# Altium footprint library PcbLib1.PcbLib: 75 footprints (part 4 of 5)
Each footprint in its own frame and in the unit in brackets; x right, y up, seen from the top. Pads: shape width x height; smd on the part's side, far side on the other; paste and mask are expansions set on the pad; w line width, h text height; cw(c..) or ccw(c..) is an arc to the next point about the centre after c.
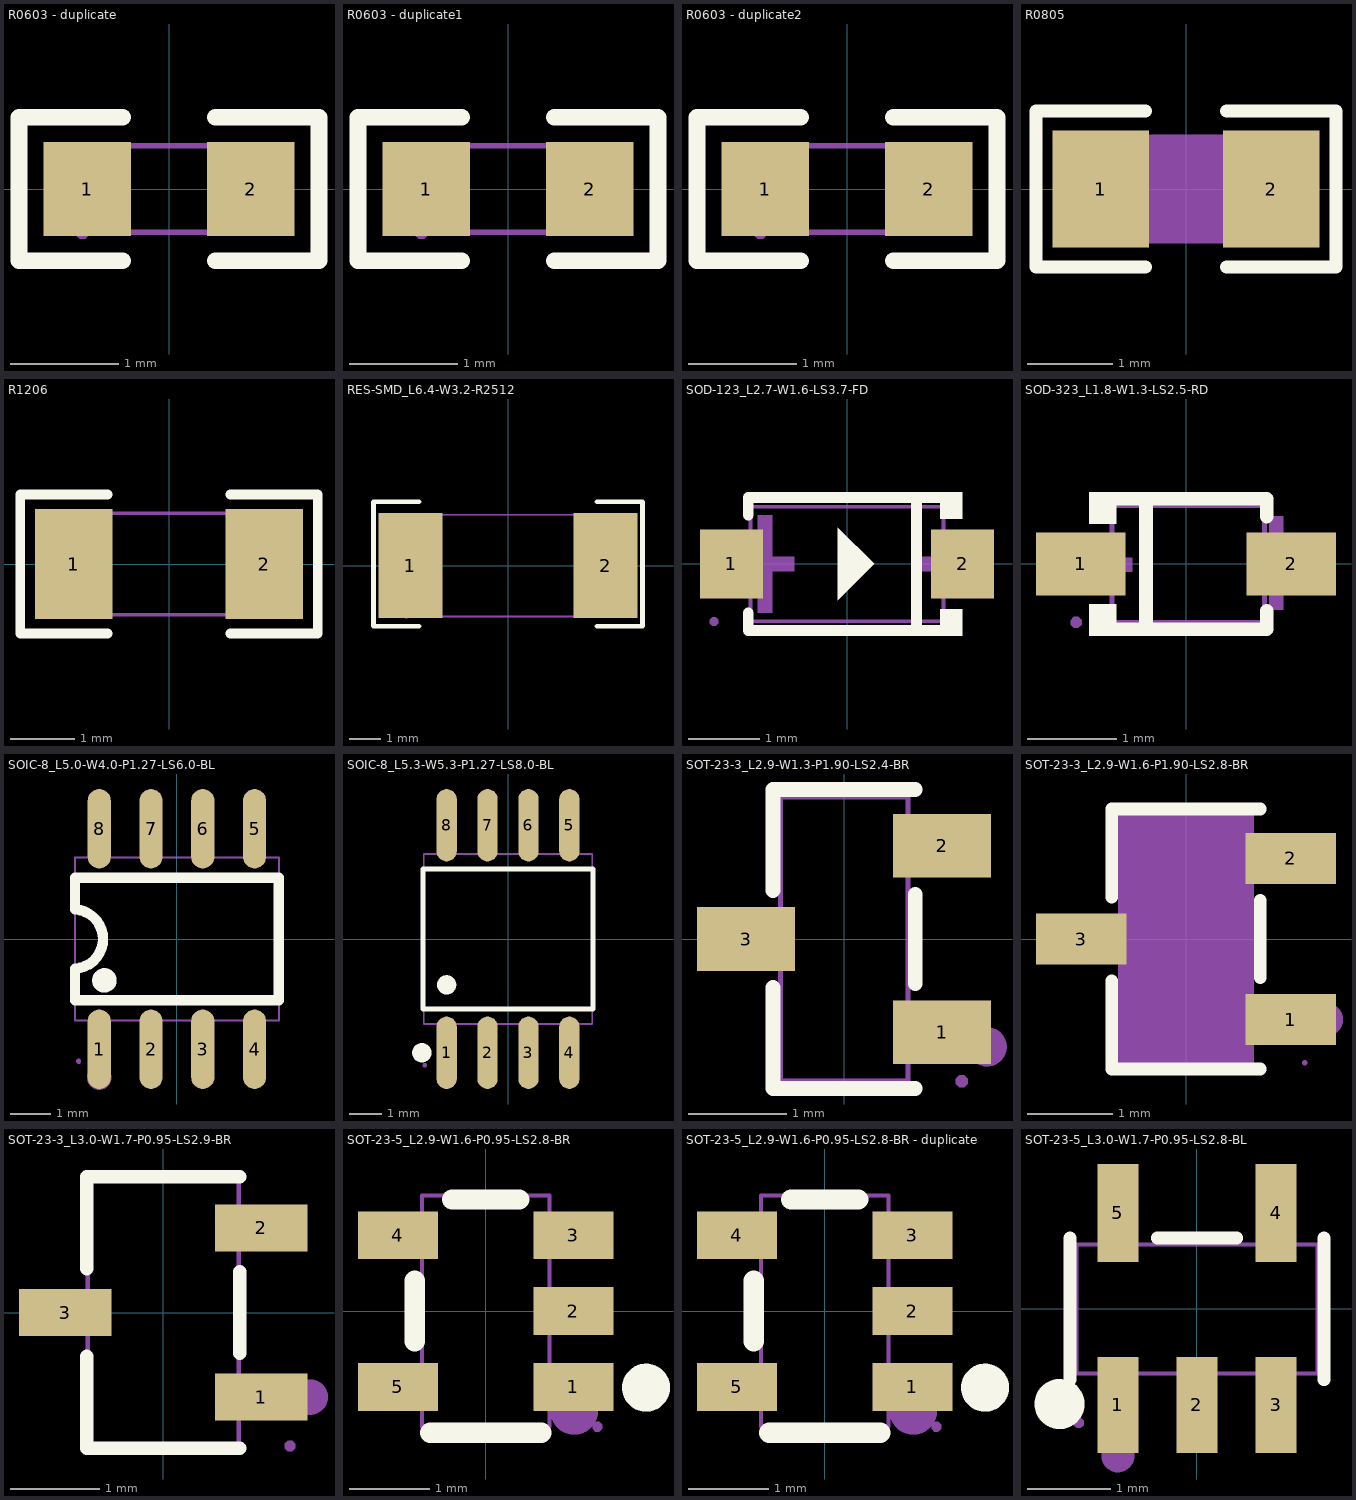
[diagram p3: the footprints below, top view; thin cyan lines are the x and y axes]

## R0603 - duplicate [mm]
pads (2):
  rect 0.806x0.864 smd paste-100 mask+0.051: 1(-0.753,0) 2(0.753,0)
Top Overlay:
  lines w0.152: -0.426,-0.661 -1.385,-0.661 -1.385,0.661 -0.426,0.661 ; 0.426,-0.661 1.385,-0.661 1.385,0.661 0.426,0.661
Top Paste:
  region: 1.195,0.45 0.395,0.45 0.345,0.4 0.345,0.172 0.715,0.172 0.715,-0.158 0.345,-0.158 0.345,-0.4 0.395,-0.45 1.195,-0.45 1.245,-0.4 1.245,0.4
  region: -1.195,-0.45 -0.395,-0.45 -0.345,-0.4 -0.345,-0.172 -0.715,-0.172 -0.715,0.158 -0.345,0.158 -0.345,0.4 -0.395,0.45 -1.195,0.45 -1.245,0.4 -1.245,-0.4
Mechanical 6:
  lines w0.051: -0.8,-0.4 -0.8,0.4 0.8,0.4 0.8,-0.4 -0.8,-0.4
Mechanical 8:
  region: -0.74,-0.4 -0.74,-0.425 -0.775,-0.46 -0.825,-0.46 -0.86,-0.425 -0.86,-0.4 -0.86,-0.375 -0.825,-0.34 -0.775,-0.34 -0.74,-0.375 -0.74,-0.4
Mechanical 9:
  region: -0.8,-0.4 -0.8,0.4 -0.5,0.4 -0.5,-0.4
  region: 0.8,-0.4 0.8,0.4 0.5,0.4 0.5,-0.4

## R0603 - duplicate1 [mm]
pads (2):
  rect 0.806x0.864 smd paste-100 mask+0.051: 1(-0.753,0) 2(0.753,0)
Top Overlay:
  lines w0.152: -0.426,-0.661 -1.385,-0.661 -1.385,0.661 -0.426,0.661 ; 0.426,-0.661 1.385,-0.661 1.385,0.661 0.426,0.661
Top Paste:
  region: -1.195,-0.45 -0.395,-0.45 -0.345,-0.4 -0.345,-0.172 -0.715,-0.172 -0.715,0.158 -0.345,0.158 -0.345,0.4 -0.395,0.45 -1.195,0.45 -1.245,0.4 -1.245,-0.4
  region: 1.195,0.45 0.395,0.45 0.345,0.4 0.345,0.172 0.715,0.172 0.715,-0.158 0.345,-0.158 0.345,-0.4 0.395,-0.45 1.195,-0.45 1.245,-0.4 1.245,0.4
Mechanical 6:
  lines w0.051: -0.8,-0.4 0.8,-0.4 0.8,0.4 -0.8,0.4 -0.8,-0.4
Mechanical 8:
  region: -0.74,-0.4 -0.74,-0.425 -0.775,-0.46 -0.825,-0.46 -0.86,-0.425 -0.86,-0.4 -0.86,-0.375 -0.825,-0.34 -0.775,-0.34 -0.74,-0.375 -0.74,-0.4
Mechanical 9:
  region: 0.8,-0.4 0.8,0.4 0.5,0.4 0.5,-0.4
  region: -0.8,-0.4 -0.8,0.4 -0.5,0.4 -0.5,-0.4

## R0603 - duplicate2 [mm]
pads (2):
  rect 0.806x0.864 smd paste-100 mask+0.051: 1(-0.753,0) 2(0.753,0)
Top Overlay:
  lines w0.152: -0.426,-0.661 -1.385,-0.661 -1.385,0.661 -0.426,0.661 ; 0.426,-0.661 1.385,-0.661 1.385,0.661 0.426,0.661
Top Paste:
  region: 1.195,0.45 0.395,0.45 0.345,0.4 0.345,0.172 0.715,0.172 0.715,-0.158 0.345,-0.158 0.345,-0.4 0.395,-0.45 1.195,-0.45 1.245,-0.4 1.245,0.4
  region: -1.195,-0.45 -0.395,-0.45 -0.345,-0.4 -0.345,-0.172 -0.715,-0.172 -0.715,0.158 -0.345,0.158 -0.345,0.4 -0.395,0.45 -1.195,0.45 -1.245,0.4 -1.245,-0.4
Mechanical 6:
  lines w0.051: -0.8,-0.4 -0.8,0.4 0.8,0.4 0.8,-0.4 -0.8,-0.4
Mechanical 8:
  region: -0.74,-0.4 -0.74,-0.425 -0.775,-0.46 -0.825,-0.46 -0.86,-0.425 -0.86,-0.4 -0.86,-0.375 -0.825,-0.34 -0.775,-0.34 -0.74,-0.375 -0.74,-0.4
Mechanical 9:
  region: -0.8,-0.4 -0.8,0.4 -0.5,0.4 -0.5,-0.4
  region: 0.8,-0.4 0.8,0.4 0.5,0.4 0.5,-0.4

## R0805 [mm]
pads (2):
  rect 1.133x1.377 smd paste-100 mask+0.051: 1(-1,0) 2(1,0)
Top Overlay:
  lines w0.152: -0.476,-0.917 -1.761,-0.917 -1.761,0.917 -0.476,0.917 ; 0.476,-0.917 1.761,-0.917 1.761,0.917 0.476,0.917
Top Paste:
  region: 0.45,-0.64 0.45,-0.22 0.895,-0.22 0.895,0.23 0.455,0.23 0.45,0.64 0.5,0.69 1.65,0.69 1.7,0.64 1.7,-0.64 1.65,-0.69 0.5,-0.69
  region: -1.7,-0.64 -1.7,0.64 -1.65,0.69 -0.5,0.69 -0.45,0.64 -0.445,0.23 -0.895,0.23 -0.895,-0.22 -0.455,-0.22 -0.45,-0.64 -0.5,-0.69 -1.65,-0.69
Mechanical 9:
  region: -1,-0.637 -1,0.637 1,0.637 1,-0.637
Mechanical 11:
  region: -0.97,-0.638 -0.97,-0.65 -0.988,-0.668 -1.012,-0.668 -1.03,-0.65 -1.03,-0.638 -1.03,-0.625 -1.012,-0.608 -0.988,-0.608 -0.97,-0.625 -0.97,-0.638
Mechanical 12:
  region: 1,-0.637 1,0.637 0.6,0.637 0.6,-0.637
  region: -1,-0.637 -1,0.637 -0.6,0.637 -0.6,-0.637

## R1206 [mm]
pads (2):
  rect 1.208x1.701 smd paste-100 mask+0.051: 1(-1.479,0) 2(1.479,0)
Top Overlay:
  lines w0.152: -0.951,-1.079 -2.311,-1.079 -2.311,1.079 -0.951,1.079 ; 0.951,-1.079 2.311,-1.079 2.311,1.079 0.951,1.079
Top Paste:
  region: 0.875,-0.75 0.875,-0.389 0.975,-0.289 1.186,-0.289 1.286,-0.189 1.286,0.189 1.186,0.289 0.975,0.289 0.875,0.389 0.875,0.75 0.975,0.85 1.983,0.85 2.083,0.75 2.083,-0.75 1.983,-0.85 0.975,-0.85
  region: -0.875,-0.75 -0.875,-0.389 -0.975,-0.289 -1.186,-0.289 -1.286,-0.189 -1.286,0.189 -1.186,0.289 -0.975,0.289 -0.875,0.389 -0.875,0.75 -0.975,0.85 -1.983,0.85 -2.083,0.75 -2.083,-0.75 -1.983,-0.85 -0.975,-0.85
Mechanical 6:
  lines w0.051: -1.55,-0.788 -1.55,0.788 1.55,0.788 1.55,-0.788 -1.55,-0.788
Mechanical 8:
  region: -1.49,-0.787 -1.49,-0.812 -1.525,-0.847 -1.575,-0.847 -1.61,-0.812 -1.61,-0.787 -1.61,-0.763 -1.575,-0.727 -1.525,-0.727 -1.49,-0.763 -1.49,-0.787
Mechanical 9:
  region: -1.55,-0.788 -1.55,0.788 -1.1,0.788 -1.1,-0.788
  region: 1.55,-0.788 1.55,0.788 1.1,0.788 1.1,-0.788

## RES-SMD_L6.4-W3.2-R2512 [mm]
pads (2):
  rect 2x3.3 smd: 1(-3.066,0) 2(3.066,0)
Top Overlay:
  lines w0.152: -2.794,-1.905 -4.229,-1.905 -4.229,2.008 -2.794,2.008 ; 2.794,-1.905 4.229,-1.905 4.229,2.008 2.794,2.008
Mechanical 6:
  lines w0.051: -3.2,-1.6 -3.2,1.6 3.2,1.6 3.2,-1.6 -3.2,-1.6
Mechanical 8:
  region: -3.14,-1.6 -3.14,-1.625 -3.175,-1.66 -3.225,-1.66 -3.26,-1.625 -3.26,-1.6 -3.26,-1.575 -3.225,-1.54 -3.175,-1.54 -3.14,-1.575 -3.14,-1.6
Mechanical 9:
  region: -3.199,1.6 -2.299,1.6 -2.299,-1.6 -3.199,-1.6
  region: 2.299,1.6 3.199,1.6 3.199,-1.6 2.299,-1.6

## SOD-123_L2.7-W1.6-LS3.7-FD [mm]
pads (2):
  rect 0.88x0.96 smd: 1(-1.61,0) 2(1.61,0)
Top Overlay:
  region: 0.381,0 -0.127,0.508 -0.127,-0.508
  region: 1.3,1.002 1.3,0.632 1.605,0.632 1.605,1.002
  region: 1.3,-1.003 1.3,-0.632 1.605,-0.633 1.605,-1.003
  lines w0.152: -1.376,-0.683 -1.376,-0.926 1.376,-0.926 ; -1.376,0.683 -1.376,0.926 1.376,0.926 ; 0.967,-0.926 0.967,0.926
Mechanical 2:
  region: -1.245,-0.68 -1.245,0.68 -1.041,0.68 -1.041,-0.68
  region: -1.551,-0.102 -1.551,0.102 -0.735,0.102 -0.735,-0.102
  region: 1.805,-0.102 1.805,0.102 0.989,0.102 0.989,-0.102
Mechanical 6:
  lines w0.051: -1.345,-0.8 -1.345,0.8 1.345,0.8 1.345,-0.8 -1.345,-0.8
Mechanical 7:
  region: -1.511,0.3 -1.511,-0.3 -1.34,-0.3 -1.34,0.3
  region: 1.511,-0.3 1.511,0.3 1.34,0.3 1.34,-0.3
Mechanical 8:
  region: -1.791,-0.8 -1.791,-0.825 -1.826,-0.86 -1.876,-0.86 -1.911,-0.825 -1.911,-0.8 -1.911,-0.775 -1.876,-0.74 -1.826,-0.74 -1.791,-0.775 -1.791,-0.8
Mechanical 9:
  region: -1.851,0.3 -1.501,0.3 -1.501,-0.3 -1.851,-0.3
  region: 1.851,-0.3 1.501,-0.3 1.501,0.3 1.851,0.3

## SOD-323_L1.8-W1.3-LS2.5-RD [mm]
pads (2):
  rect 1x0.7 smd: 1(-1.172,0) 2(1.172,0)
Top Overlay:
  region: -0.775,0.802 -0.775,0.45 -1.08,0.45 -1.08,0.802
  region: -0.775,-0.803 -0.775,-0.45 -1.08,-0.45 -1.08,-0.803
  lines w0.152: -0.851,-0.726 0.901,-0.726 0.901,-0.52 ; -0.851,0.726 0.901,0.726 0.901,0.53 ; -0.447,-0.726 -0.447,0.726
Mechanical 2:
  region: -1.225,0.07 -1.225,-0.086 -0.601,-0.086 -0.601,0.07
  region: 1.315,0.09 1.315,-0.066 0.691,-0.066 0.691,0.09
  region: 1.083,0.53 1.083,-0.51 0.927,-0.51 0.927,0.53
Mechanical 6:
  lines w0.051: -0.825,-0.65 -0.825,0.65 0.875,0.65 0.875,-0.65 -0.825,-0.65
Mechanical 7:
  region: 0.985,0.16 0.985,-0.16 0.865,-0.16 0.865,0.16
  region: -0.815,0.16 -0.815,-0.16 -0.935,-0.16 -0.935,0.16
Mechanical 8:
  region: -1.165,-0.65 -1.165,-0.675 -1.2,-0.71 -1.25,-0.71 -1.285,-0.675 -1.285,-0.65 -1.285,-0.625 -1.25,-0.59 -1.2,-0.59 -1.165,-0.625 -1.165,-0.65
Mechanical 9:
  region: 1.275,0.16 1.275,-0.16 0.975,-0.16 0.975,0.16
  region: -0.925,0.16 -0.925,-0.16 -1.225,-0.16 -1.225,0.16

## SOIC-8_L5.0-W4.0-P1.27-LS6.0-BL [mil]
pads (8):
  oval 22.38x76.78 smd: 1(-75,-106.5) 2(-25,-106.5) 3(25,-106.5) 4(75,-106.5) 5(75,106.5) 6(25,106.5) 7(-25,106.5) 8(-75,106.5)
Top Overlay:
  circle w11.81: c-70,-40 r5.91
  lines w10: -98.43,-28.61 ccw(c-99.99,0) -98.23,28.59 ; -98.42,-28.61 -98.42,-59.05 98.42,-59.05 98.42,59.05 -98.42,59.05 -98.42,28.59
Mechanical 2:
  circle w11.81: c-75,-133.86 r5.91
Mechanical 6:
  lines w2: -98.42,-78.74 98.42,-78.74 98.42,78.74 -98.42,78.74 -98.42,-78.74
Mechanical 7:
  region: -83.07,-85.63 -83.07,-76.38 -66.93,-76.38 -66.93,-85.63
  region: -33.07,-85.63 -33.07,-76.38 -16.93,-76.38 -16.93,-85.63
  region: 16.93,-85.63 16.93,-76.38 33.07,-76.38 33.07,-85.63
  region: 66.93,-85.63 66.93,-76.38 83.07,-76.38 83.07,-85.63
  region: -83.07,76.38 -83.07,85.63 -66.93,85.63 -66.93,76.38
  region: -33.07,76.38 -33.07,85.63 -16.93,85.63 -16.93,76.38
  region: 16.93,76.38 16.93,85.63 33.07,85.63 33.07,76.38
  region: 66.93,76.38 66.93,85.63 83.07,85.63 83.07,76.38
Mechanical 8:
  region: -92.64,-118.11 -92.64,-119.09 -94.02,-120.47 -95.98,-120.47 -97.36,-119.09 -97.36,-118.11 -97.36,-117.13 -95.98,-115.75 -94.02,-115.75 -92.64,-117.13 -92.64,-118.11
Mechanical 9:
  region: -83.07,-118.11 -83.07,-85.24 -66.93,-85.24 -66.93,-118.11
  region: -33.07,-118.11 -33.07,-85.24 -16.93,-85.24 -16.93,-118.11
  region: 16.93,-118.11 16.93,-85.24 33.07,-85.24 33.07,-118.11
  region: 66.93,-118.11 66.93,-85.24 83.07,-85.24 83.07,-118.11
  region: -83.07,85.24 -83.07,118.11 -66.93,118.11 -66.93,85.24
  region: -33.07,85.24 -33.07,118.11 -16.93,118.11 -16.93,85.24
  region: 16.93,85.24 16.93,118.11 33.07,118.11 33.07,85.24
  region: 66.93,85.24 66.93,118.11 83.07,118.11 83.07,85.24

## SOIC-8_L5.3-W5.3-P1.27-LS8.0-BL [mm]
pads (8):
  oval 0.63x2.25 smd: 1(-1.905,-3.53) 2(-0.635,-3.53) 3(0.635,-3.53) 4(1.905,-3.53) 5(1.905,3.53) 6(0.635,3.53) 7(-0.635,3.53) 8(-1.905,3.53)
Top Overlay:
  circle w0.3: c-2.672,-3.53 r0.15
  circle w0.3: c-1.905,-1.424 r0.15
  lines w0.152: -2.639,-2.176 2.639,-2.176 2.639,2.176 -2.639,2.176 -2.639,-2.176
Mechanical 2:
  circle w0.3: c-1.905,-4.35 r0.15
Mechanical 6:
  lines w0.051: -2.615,-2.64 2.615,-2.64 2.615,2.64 -2.615,2.64 -2.615,-2.64
Mechanical 7:
  region: 1.68,3.31 1.68,2.595 2.13,2.595 2.13,3.31
  region: 0.41,3.31 0.41,2.595 0.86,2.595 0.86,3.31
  region: -0.86,3.31 -0.86,2.595 -0.41,2.595 -0.41,3.31
  region: -2.13,3.31 -2.13,2.595 -1.68,2.595 -1.68,3.31
  region: 1.68,-3.31 1.68,-2.595 2.13,-2.595 2.13,-3.31
  region: 0.41,-3.31 0.41,-2.595 0.86,-2.595 0.86,-3.31
  region: -0.86,-3.31 -0.86,-2.595 -0.41,-2.595 -0.41,-3.31
  region: -2.13,-3.31 -2.13,-2.595 -1.68,-2.595 -1.68,-3.31
Mechanical 8:
  region: -2.525,-3.92 -2.525,-3.945 -2.56,-3.98 -2.61,-3.98 -2.645,-3.945 -2.645,-3.92 -2.645,-3.895 -2.61,-3.86 -2.56,-3.86 -2.525,-3.895 -2.525,-3.92
Mechanical 9:
  region: 1.68,3.95 1.68,3.3 2.13,3.3 2.13,3.95
  region: 0.41,3.95 0.41,3.3 0.86,3.3 0.86,3.95
  region: -0.86,3.95 -0.86,3.3 -0.41,3.3 -0.41,3.95
  region: -2.13,3.95 -2.13,3.3 -1.68,3.3 -1.68,3.95
  region: 1.68,-3.95 1.68,-3.3 2.13,-3.3 2.13,-3.95
  region: 0.41,-3.95 0.41,-3.3 0.86,-3.3 0.86,-3.95
  region: -0.86,-3.95 -0.86,-3.3 -0.41,-3.3 -0.41,-3.95
  region: -2.13,-3.95 -2.13,-3.3 -1.68,-3.3 -1.68,-3.95

## SOT-23-3_L2.9-W1.3-P1.90-LS2.4-BR [mm]
pads (3):
  rect 1x0.65 smd: 1(1,-0.95) 2(1,0.95) 3(-1,0)
Top Overlay:
  lines w0.152: -0.726,-0.495 -0.726,-1.526 0.726,-1.526 ; -0.726,0.495 -0.726,1.526 0.726,1.526 ; 0.726,-0.455 0.726,0.455
Mechanical 2:
  circle w0.2: c1.46,-1.1 r0.1
Mechanical 6:
  lines w0.051: -0.65,-1.45 -0.65,1.45 0.65,1.45 0.65,-1.45 -0.65,-1.45
Mechanical 7:
  region: 0.64,0.735 0.64,1.165 0.91,1.165 0.91,0.735
  region: 0.64,-1.165 0.64,-0.735 0.91,-0.735 0.91,-1.165
  region: -0.91,-0.215 -0.91,0.215 -0.64,0.215 -0.64,-0.215
Mechanical 8:
  region: 1.26,-1.45 1.26,-1.475 1.225,-1.51 1.175,-1.51 1.14,-1.475 1.14,-1.45 1.14,-1.425 1.175,-1.39 1.225,-1.39 1.26,-1.425 1.26,-1.45
Mechanical 9:
  region: 0.9,0.735 0.9,1.165 1.2,1.165 1.2,0.735
  region: 0.9,-1.165 0.9,-0.735 1.2,-0.735 1.2,-1.165
  region: -1.2,-0.215 -1.2,0.215 -0.9,0.215 -0.9,-0.215

## SOT-23-3_L2.9-W1.6-P1.90-LS2.8-BR [mm]
pads (3):
  rect 1.07x0.6 smd paste+0 mask+0.051: 1(1.235,-0.95) 2(1.235,0.95) 3(-1.235,0)
Top Overlay:
  lines w0.152: -0.876,-0.495 -0.876,-1.536 0.876,-1.536 ; -0.876,0.495 -0.876,1.536 0.876,1.536 ; 0.876,-0.455 0.876,0.455
Mechanical 5:
  circle w0.2: c1.651,-0.95 r0.1
Mechanical 9:
  region: -0.8,-1.46 -0.8,1.46 0.8,1.46 0.8,-1.46
Mechanical 10:
  region: 0.79,-1.15 0.79,-0.75 0.96,-0.75 0.96,-1.15
  region: 0.79,0.75 0.79,1.15 0.96,1.15 0.96,0.75
  region: -0.96,-0.2 -0.96,0.2 -0.79,0.2 -0.79,-0.2
Mechanical 11:
  region: 1.43,-1.46 1.43,-1.472 1.412,-1.49 1.388,-1.49 1.37,-1.472 1.37,-1.46 1.37,-1.448 1.388,-1.43 1.412,-1.43 1.43,-1.448 1.43,-1.46
Mechanical 12:
  region: 0.95,-1.15 0.95,-0.75 1.4,-0.75 1.4,-1.15
  region: 0.95,0.75 0.95,1.15 1.4,1.15 1.4,0.75
  region: -0.95,-0.2 -0.95,0.2 -1.4,0.2 -1.4,-0.2

## SOT-23-3_L3.0-W1.7-P0.95-LS2.9-BR [mm]
pads (3):
  rect 1.037x0.532 smd: 1(1.101,-0.95) 2(1.101,0.95) 3(-1.101,0)
Top Overlay:
  lines w0.152: -0.859,-0.495 -0.859,-1.526 0.859,-1.526 ; -0.859,0.495 -0.859,1.526 0.859,1.526 ; 0.859,-0.455 0.859,0.455
Mechanical 2:
  circle w0.2: c1.65,-0.95 r0.1
Mechanical 6:
  lines w0.051: -0.85,-1.5 -0.85,1.5 0.85,1.5 0.85,-1.5 -0.85,-1.5
Mechanical 7:
  region: 0.815,-1.137 0.815,-0.762 1.01,-0.762 1.01,-1.137
  region: 0.815,0.762 0.815,1.137 1.01,1.137 1.01,0.762
  region: -1.01,-0.188 -1.01,0.188 -0.815,0.188 -0.815,-0.188
Mechanical 8:
  region: 1.485,-1.5 1.485,-1.525 1.45,-1.56 1.4,-1.56 1.365,-1.525 1.365,-1.5 1.365,-1.475 1.4,-1.44 1.45,-1.44 1.485,-1.475 1.485,-1.5
Mechanical 9:
  region: 1,-1.137 1,-0.762 1.425,-0.762 1.425,-1.137
  region: 1,0.762 1,1.137 1.425,1.137 1.425,0.762
  region: -1.425,-0.188 -1.425,0.188 -1,0.188 -1,-0.188

## SOT-23-5_L2.9-W1.6-P0.95-LS2.8-BR [mm]
pads (5):
  rect 1x0.6 smd paste+0 mask+0.05: 1(1.1,-0.95) 2(1.1,0) 3(1.1,0.95) 4(-1.1,0.95) 5(-1.1,-0.95)
Top Overlay:
  circle w0.3: c2.01,-0.96 r0.15
  lines w0.254: -0.889,-0.381 -0.889,0.381 ; -0.699,-1.524 0.698,-1.524 ; -0.422,1.397 0.422,1.397
Mechanical 2:
  circle w0.3: c1.11,-1.25 r0.15
Mechanical 6:
  lines w0.051: -0.8,-1.45 -0.8,1.45 0.8,1.45 0.8,-1.45 -0.8,-1.45
Mechanical 7:
  region: 0.96,-0.2 0.79,-0.2 0.79,0.2 0.96,0.2
  region: 0.96,0.75 0.79,0.75 0.79,1.15 0.96,1.15
  region: 0.96,-1.15 0.79,-1.15 0.79,-0.75 0.96,-0.75
  region: -0.79,0.75 -0.96,0.75 -0.96,1.15 -0.79,1.15
  region: -0.79,-1.15 -0.96,-1.15 -0.96,-0.75 -0.79,-0.75
Mechanical 8:
  region: 1.46,-1.45 1.46,-1.475 1.425,-1.51 1.375,-1.51 1.34,-1.475 1.34,-1.45 1.34,-1.425 1.375,-1.39 1.425,-1.39 1.46,-1.425 1.46,-1.45
Mechanical 9:
  region: 1.4,-0.2 0.95,-0.2 0.95,0.2 1.4,0.2
  region: 1.4,0.75 0.95,0.75 0.95,1.15 1.4,1.15
  region: 1.4,-1.15 0.95,-1.15 0.95,-0.75 1.4,-0.75
  region: -0.95,0.75 -1.4,0.75 -1.4,1.15 -0.95,1.15
  region: -0.95,-1.15 -1.4,-1.15 -1.4,-0.75 -0.95,-0.75

## SOT-23-5_L2.9-W1.6-P0.95-LS2.8-BR - duplicate [mm]
pads (5):
  rect 1x0.6 smd paste+0 mask+0.05: 1(1.1,-0.95) 2(1.1,0) 3(1.1,0.95) 4(-1.1,0.95) 5(-1.1,-0.95)
Top Overlay:
  circle w0.3: c2.01,-0.96 r0.15
  lines w0.254: -0.889,-0.381 -0.889,0.381 ; -0.699,-1.524 0.698,-1.524 ; -0.422,1.397 0.422,1.397
Mechanical 2:
  circle w0.3: c1.11,-1.25 r0.15
Mechanical 6:
  lines w0.051: -0.8,-1.45 0.8,-1.45 0.8,1.45 -0.8,1.45 -0.8,-1.45
Mechanical 7:
  region: -0.79,-1.15 -0.96,-1.15 -0.96,-0.75 -0.79,-0.75
  region: -0.79,0.75 -0.96,0.75 -0.96,1.15 -0.79,1.15
  region: 0.96,-1.15 0.79,-1.15 0.79,-0.75 0.96,-0.75
  region: 0.96,0.75 0.79,0.75 0.79,1.15 0.96,1.15
  region: 0.96,-0.2 0.79,-0.2 0.79,0.2 0.96,0.2
Mechanical 8:
  region: 1.46,-1.45 1.46,-1.475 1.425,-1.51 1.375,-1.51 1.34,-1.475 1.34,-1.45 1.34,-1.425 1.375,-1.39 1.425,-1.39 1.46,-1.425 1.46,-1.45
Mechanical 9:
  region: -0.95,-1.15 -1.4,-1.15 -1.4,-0.75 -0.95,-0.75
  region: -0.95,0.75 -1.4,0.75 -1.4,1.15 -0.95,1.15
  region: 1.4,-1.15 0.95,-1.15 0.95,-0.75 1.4,-0.75
  region: 1.4,0.75 0.95,0.75 0.95,1.15 1.4,1.15
  region: 1.4,-0.2 0.95,-0.2 0.95,0.2 1.4,0.2

## SOT-23-5_L3.0-W1.7-P0.95-LS2.8-BL [mm]
pads (5):
  rect 0.49x1.157 smd: 1(-0.95,-1.154) 2(0,-1.154) 3(0.95,-1.154)
  rect 0.49x1.175 smd: 4(0.95,1.154) 5(-0.95,1.154)
Top Overlay:
  circle w0.3: c-1.651,-1.143 r0.15
  lines w0.152: -1.526,-0.851 -1.526,0.851 ; -0.476,0.851 0.476,0.851 ; 1.526,-0.851 1.526,0.851
Mechanical 2:
  circle w0.2: c-0.95,-1.763 r0.1
Mechanical 6:
  lines w0.051: -1.45,-0.775 -1.45,0.775 1.45,0.775 1.45,-0.775 -1.45,-0.775
Mechanical 7:
  region: -1.125,-1.01 -1.125,-0.74 -0.775,-0.74 -0.775,-1.01
  region: -0.175,-1.01 -0.175,-0.74 0.175,-0.74 0.175,-1.01
  region: 0.775,-1.01 0.775,-0.74 1.125,-0.74 1.125,-1.01
  region: 0.775,0.74 0.775,1.01 1.125,1.01 1.125,0.74
  region: -1.125,0.74 -1.125,1.01 -0.775,1.01 -0.775,0.74
Mechanical 8:
  region: -1.36,-1.37 -1.36,-1.395 -1.395,-1.43 -1.445,-1.43 -1.48,-1.395 -1.48,-1.37 -1.48,-1.345 -1.445,-1.31 -1.395,-1.31 -1.36,-1.345 -1.36,-1.37
Mechanical 9:
  region: -1.125,-1.4 -1.125,-1 -0.775,-1 -0.775,-1.4
  region: -0.175,-1.4 -0.175,-1 0.175,-1 0.175,-1.4
  region: 0.775,-1.4 0.775,-1 1.125,-1 1.125,-1.4
  region: 0.775,1 0.775,1.4 1.125,1.4 1.125,1
  region: -1.125,1 -1.125,1.4 -0.775,1.4 -0.775,1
